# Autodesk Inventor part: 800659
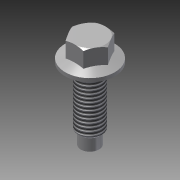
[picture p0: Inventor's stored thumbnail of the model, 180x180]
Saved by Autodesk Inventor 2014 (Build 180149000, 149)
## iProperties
Created: 2007-11
Part Number: 800659
Document SubType Name: Modeling
Designer: TH
Density: 8.08 g/cm^3
Mass: 32.4694 g
Surface Area: 19.7101 cm^2
Volume: 4.01849 cm^3
Material: Stainless Steel
Description: H343 BOLT M12 X 20
Appearance: Steel
Component Category: Fasteners
Author: TH
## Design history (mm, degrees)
sketch "Sketch1"
  geometry: L1 (-10.508, 0)-(10.508, 0) reference; L2 (7.506, 0)-(3.753, -6.5); L3 (3.753, -6.5)-(-3.753, -6.5); L4 (-3.753, -6.5)-(-7.506, 0); L5 (-7.506, 0)-(-3.753, 6.5); L6 (-3.753, 6.5)-(3.753, 6.5); L7 (3.753, 6.5)-(7.506, 0); 2 further points
  constraints: 12 end point, 1 coincident, 1 point on line, 13 other
  dimensions: "d0" = 13 distance between parallel lines of L3 L6
extrude "Extrusion1" new body sketch "Sketch1" distance "d1" = 9.7; taper "d2" = 0 deg
sketch "Sketch2"
  geometry: L1 (3.753, -9.7)-(-3.753, -9.7) reference; L2 (7.506, -9.7)-(3.753, -9.7) reference; L3 (3.753, -9.7)-(7.506, -9.7) reference; L4 (-3.753, -9.7)-(3.753, -9.7) reference; L5 (-7.506, -9.7)-(-3.753, -9.7) reference; L6 (-3.753, -9.7)-(-7.506, -9.7) reference; L7 (0, -9.7)-(-10.4, -9.7); L8 (-10.4, -9.7)-(-10.4, -8.2); L9 (-10.4, -8.2)-(0, -3.892); L10 (0, -3.892)-(0, -9.7); L11 (-5, -9.7)-(-5, -33.55); L12 (-5, -33.55)-(-3.85, -34.7); L13 (-3.85, -34.7)-(-3.85, -39.7); L14 (-3.85, -39.7)-(0, -39.7); L15 (0, -9.7)-(0, -39.7); 1 further point
  constraints: 18 end point, 4 perpendicular, 2 parallel, 2 point on line, 1 midpoint
  dimensions: "d3" = 1.5 distance of L7.end L8.end; "d4" = 10.4 distance of L7.start L7.end; "d5" = 22.5 deg angle of L7 L9; "d7" = 5 distance between parallel lines of L15 L11; "d8" = 3.85 distance between parallel lines of L15 L13; "d9" = 30 distance between parallel lines of L7 L14; "d10" = 5 distance from line of L12.end L14; "d11" = 1.15 horizontal distance of L11.end L12.end
revolve "Revolution1" sketch "Sketch2" stored, may be unused: angle "d12" = 90 deg
sketch "Sketch3"
  geometry: L1 (-6.5, 0)-(-7.506, -0.581); L2 (-7.506, -0.581)-(-7.506, 0); L3 (-7.506, 0)-(-6.5, 0); L4 (0, -47.64)-(0, 7.94) reference; 1 further point
  constraints: 6 end point, 1 perpendicular, 1 point on line, 1 vertical
  dimensions: "d13" = 30 deg angle of L1 L3; "d14" = 1.00555 distance of L2.end L1.start; "d16" = 6.5 distance of L1.start point (0, 0)
revolve "Revolution2" sketch "Sketch3" stored, may be unused: angle "d17" = 90 deg
thread "Thread1" dims "d18" = 10, "d19" = 0
fillet "Fillet1" dims "d20" = 0.2
body "Solid1"
node "Projected Loop1"
